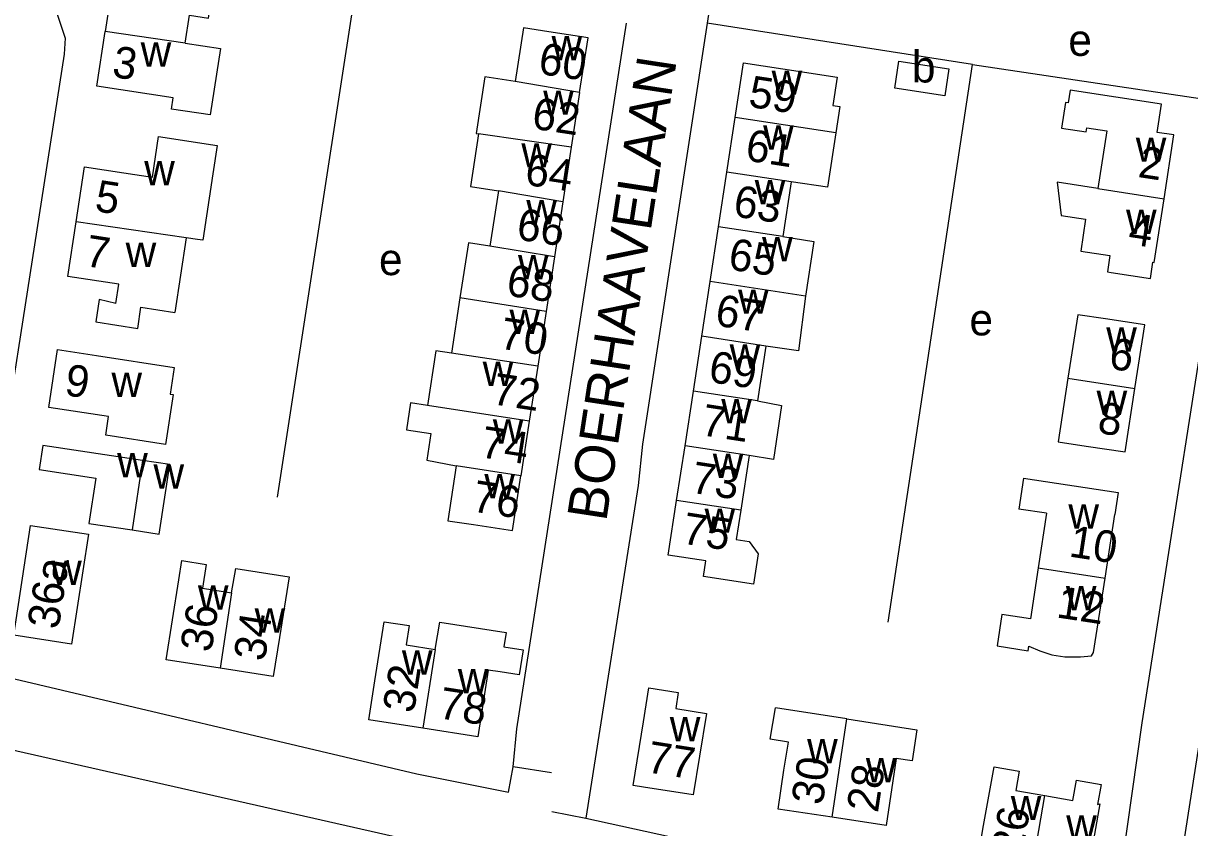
# Model space of a CAD drawing. Extents: x 161093 to 163177, y 379000 to 380904.
# Drawn here: x 161921.7 to 162069, y 380393.8 to 380495.5 of the extents above; entities that cross this region are included whole.
import ezdxf

# ---------------------------------------------------------------- set-up
doc = ezdxf.new("R2010")
doc.units = 0
for name, color, linetype in [('BLT_Basislijn', 7, 'Continuous'), ('BLT_Bebouwing', 7, 'Continuous'), ('BLT_Centroide', 7, 'Continuous'), ('BLT_Huisnummer', 7, 'Continuous'), ('BLT_Huisnummer_ tussenligend', 7, 'Continuous'), ('BLT_Onderverdeling_panden', 7, 'Continuous'), ('BLT_Straatnaam', 7, 'Continuous')]:
    doc.layers.add(name, color=color, linetype=linetype)

msp = doc.modelspace()

# ---------------------------------------------------------------- linework, layer by layer
at = {"layer": 'BLT_Basislijn'}
for p, q in [((162011.73, 380519.84), (162008.05, 380495.48)), ((161953.76, 380435.58), (161963.84, 380501.05)), ((162041.6, 380490.28), (162008.05, 380495.48)), ((162041.6, 380490.28), (162080.66, 380484.4)), ((162080.1, 380468.07), (162066.51, 380380.82)), ((161988.39, 380400.71), (161983.54, 380401.47)), ((161988.42, 380395.82), (161992.72, 380394.99))]:
    msp.add_line(p, q, dxfattribs=at)
for points in [[(161922.51, 380507.63), (161922.58, 380506.72), (161926.97, 380493.62), (161926.83, 380491.57), (161914.93, 380415.47), (161916.11, 380414.16), (161917.48, 380413.33), (161971.38, 380400.58), (161982.94, 380398.28), (161983.54, 380401.47)], [(161983.54, 380401.47), (161984.03, 380406.27), (161997.87, 380495.51)], [(162008.05, 380495.48), (161999.88, 380442.25), (161999.34, 380437.05), (161992.72, 380394.99)], [(162030.93, 380419.77), (162041.6, 380490.28)], [(161992.72, 380394.99), (162053.82, 380381.59), (162056.59, 380381.51), (162058.47, 380382.47), (162059.9, 380384.99), (162063, 380407.02), (162073.67, 380475.15), (162080.66, 380484.4)], [(161790.41, 380429.73), (161841.6, 380420.4), (161892.77, 380409.85), (161973.76, 380391.48), (162004.17, 380383.95)]]:
    msp.add_lwpolyline(points, dxfattribs=at)
at = {"layer": 'BLT_Bebouwing'}
for p, q in [((162032.27, 380490.7), (162038.6, 380489.73)), ((161991.95, 380486.73), (161990.89, 380479.81)), ((162010.55, 380476.67), (162011.61, 380483.59)), ((161990.89, 380479.81), (161989.83, 380472.89)), ((162009.49, 380469.75), (162010.55, 380476.67)), ((161981.69, 380474.29), (161980.62, 380467.32)), ((162018.66, 380475.43), (162017.6, 380468.51)), ((161989.83, 380472.89), (161988.77, 380465.96)), ((161927.3, 380463.47), (161928.35, 380470.39)), ((162008.43, 380462.83), (162009.49, 380469.75)), ((161942.25, 380468.36), (161940.81, 380458.92)), ((161988.77, 380465.96), (161987.71, 380459.04)), ((161933.73, 380462.49), (161927.3, 380463.47)), ((162007.38, 380455.91), (162008.43, 380462.83)), ((161976.83, 380460.78), (161975.75, 380453.76)), ((161987.71, 380459.04), (161986.65, 380452.11)), ((162006.32, 380448.99), (162007.38, 380455.91)), ((162015.48, 380454.67), (162014.42, 380447.75)), ((161986.65, 380452.11), (161985.58, 380445.19)), ((162005.26, 380442.07), (162006.32, 380448.99)), ((161985.58, 380445.19), (161984.52, 380438.27)), ((162004.2, 380435.15), (162005.26, 380442.07)), ((162013.36, 380440.83), (162012.31, 380433.91)), ((162050.93, 380433.53), (162047.43, 380434.07))]:
    msp.add_line(p, q, dxfattribs=at)
for points in [[(161942.01, 380500), (161938, 380500.61), (161933.05, 380501.36), (161932, 380494.44)], [(161942.11, 380492.98), (161942.65, 380496.5), (161945.08, 380496.13), (161945.57, 380499.35), (161942.01, 380500)], [(161991.95, 380486.73), (161993.01, 380493.65), (161988.07, 380494.41), (161984.85, 380494.9), (161983.81, 380488.11)], [(161942.11, 380492.98), (161946.56, 380492.3), (161945.28, 380483.89), (161940.37, 380484.63), (161940.58, 380486.06), (161930.95, 380487.52), (161932, 380494.44)], [(162011.61, 380483.59), (162012.67, 380490.5), (162017.61, 380489.74), (162024.5, 380488.69), (162023.95, 380485.1), (162024.82, 380484.97), (162024.31, 380481.64)], [(162038.6, 380489.73), (162038.08, 380486.32), (162031.75, 380487.29), (162032.27, 380490.7)], [(161983.81, 380488.11), (161979.98, 380488.7), (161978.88, 380481.53), (161979.18, 380481.49)], [(162065.78, 380473.3), (162067.01, 380481.36), (162064.93, 380481.67), (162065.48, 380485.26), (162053.93, 380487.03), (162053.68, 380485.42), (162053.33, 380485.47), (162052.83, 380482.24), (162055.95, 380481.77), (162056.02, 380482.25), (162058.54, 380481.87), (162057.42, 380474.58)], [(161979.18, 380481.49), (161978.16, 380474.83), (161981.69, 380474.29)], [(162024.31, 380481.64), (162023.28, 380474.76), (162018.66, 380475.43)], [(161928.35, 380470.39), (161929.41, 380477.32), (161934.35, 380476.56), (161937.97, 380476.01), (161938.75, 380481.15), (161946.17, 380480.02), (161945.62, 380476.45), (161944.35, 380468.05), (161943.69, 380468.14), (161942.25, 380468.36)], [(162057.42, 380474.58), (162052.27, 380475.39), (162052.8, 380471.18), (162055.87, 380470.71), (162055.25, 380466.68), (162058.94, 380466.11), (162058.62, 380464.04), (162059.12, 380463.96), (162064.06, 380463.21), (162064.38, 380465.28), (162064.55, 380465.25), (162065.78, 380473.3)], [(162017.6, 380468.51), (162021.55, 380467.9), (162020.49, 380460.98)], [(161980.62, 380467.32), (161977.9, 380467.74), (161976.83, 380460.78)], [(161933.37, 380460.05), (161933.73, 380462.49)], [(162020.49, 380460.98), (162019.6, 380454.07), (162015.48, 380454.67)], [(161933.37, 380460.05), (161931.25, 380460.58), (161930.81, 380457.72), (161936.13, 380456.91), (161936.53, 380459.57), (161940.81, 380458.92)], [(162062.11, 380449.31), (162063.34, 380457.34), (162058.39, 380458.1), (162054.87, 380458.64), (162053.64, 380450.61)], [(161930.92, 380453.48), (161940.73, 380451.98), (161940.21, 380448.59), (161940.59, 380448.53), (161939.63, 380442.24), (161932.07, 380443.4), (161932.43, 380445.77), (161924.87, 380446.92), (161925.98, 380454.23), (161930.92, 380453.48)], [(161975.75, 380453.76), (161973.8, 380454.06), (161972.74, 380447.15)], [(162053.64, 380450.61), (162052.41, 380442.57), (162055.93, 380442.03), (162060.88, 380441.28), (162062.11, 380449.31)], [(161970.6, 380447.48), (161970.08, 380444.1), (161973.15, 380443.63), (161972.63, 380440.25), (161976.36, 380439.52)], [(161972.74, 380447.15), (161970.6, 380447.48)], [(162014.42, 380447.75), (162017.47, 380447.14), (162016.43, 380440.34), (162013.36, 380440.83)], [(161936.74, 380440.2), (161924.14, 380442.12), (161923.67, 380439.05), (161930.81, 380437.96)], [(161935.4, 380431.42), (161938.82, 380430.9), (161940.16, 380439.68), (161936.74, 380440.2)], [(161976.36, 380439.52), (161975.3, 380432.59), (161978.52, 380432.1), (161983.46, 380431.34), (161984.52, 380438.27)], [(161930.81, 380437.96), (161929.94, 380432.25), (161935.4, 380431.42)], [(162048.03, 380437.99), (162047.43, 380434.07)], [(162048.03, 380437.99), (162059.99, 380436.16), (162059.57, 380433.39)], [(162012.31, 380433.91), (162011.74, 380430.21), (162013.38, 380429.96), (162014.5, 380428.4), (162013.91, 380424.55), (162007.58, 380425.52), (162007.88, 380427.5), (162003.14, 380428.23), (162004.2, 380435.15)], [(162050.93, 380433.53), (162049.87, 380426.63)], [(162058.33, 380425.33), (162059.57, 380433.39)], [(161922.59, 380431.99), (161929.88, 380430.88), (161927.77, 380416.99), (161920.48, 380418.1), (161922.59, 380431.99)], [(161946.54, 380413.95), (161939.73, 380415.02), (161941.31, 380425.1), (161941.69, 380427.54), (161944.77, 380427.06), (161944.29, 380424.04), (161947.98, 380423.46)], [(161947.98, 380423.46), (161948.52, 380426.54), (161955.23, 380425.49), (161954.03, 380417.84), (161953.25, 380412.9), (161946.54, 380413.95)], [(162049.87, 380426.63), (162048.89, 380420.19), (162045.3, 380420.74), (162044.69, 380416.75), (162048.6, 380416.15), (162048.68, 380416.71), (162050.1, 380416.13), (162051.6, 380415.64), (162053.25, 380415.39), (162055.21, 380415.38), (162056.6, 380415.51), (162056.89, 380415.93), (162058.33, 380425.33)], [(161972.13, 380406.35), (161965.32, 380407.41), (161966.09, 380412.35), (161967.25, 380419.8), (161970.41, 380419.32), (161970.03, 380416.88), (161973.68, 380416.31)], [(161973.68, 380416.31), (161974.29, 380419.76), (161982.66, 380418.46), (161982.38, 380416.64), (161984.8, 380416.27), (161984.31, 380413.11), (161981.89, 380413.48), (161980.41, 380413.71), (161979.1, 380405.27), (161972.13, 380406.35)], [(162000, 380407.14), (162000.69, 380411.45), (162004.41, 380410.85), (162004.09, 380408.83), (162007.97, 380408.21), (162007.11, 380402.84), (162006.31, 380397.91), (162000, 380398.91)], [(162018.34, 380404.58), (162016.03, 380404.97), (162016.69, 380408.94)], [(162025.71, 380407.53), (162016.69, 380408.94)], [(162000, 380398.91), (161998.71, 380399.11), (162000, 380407.14)], [(162025.71, 380407.53), (162034.55, 380406.15), (162033.96, 380402.21), (162031.94, 380402.51), (162030.67, 380394.06), (162023.84, 380395.09)], [(162023.84, 380395.09), (162017.01, 380396.11), (162017.75, 380401.06), (162018.34, 380404.58)], [(162049.02, 380387.92), (162042.12, 380389.12), (162042.98, 380394.05), (162044.32, 380401.47), (162047.48, 380400.92), (162047.05, 380398.47), (162050.73, 380397.83)], [(162050.73, 380397.83), (162054.27, 380397.22), (162054.72, 380399.77), (162057.82, 380399.23), (162057.38, 380396.7), (162057.65, 380396.8), (162055.91, 380386.73), (162049.02, 380387.92)]]:
    msp.add_lwpolyline(points, dxfattribs=at)
at = {"layer": 'BLT_Onderverdeling_panden'}
for p, q in [((161942.11, 380492.98), (161932, 380494.44)), ((161991.95, 380486.73), (161983.81, 380488.11)), ((162024.31, 380481.64), (162011.61, 380483.59)), ((161990.89, 380479.81), (161979.18, 380481.49)), ((162018.66, 380475.43), (162010.55, 380476.67)), ((161989.83, 380472.89), (161981.69, 380474.29)), ((162057.42, 380474.58), (162065.78, 380473.3)), ((161942.25, 380468.36), (161928.35, 380470.39)), ((162017.6, 380468.51), (162009.49, 380469.75)), ((161988.77, 380465.96), (161980.62, 380467.32)), ((162020.49, 380460.98), (162008.43, 380462.83)), ((161987.71, 380459.04), (161976.83, 380460.78)), ((162015.48, 380454.67), (162007.38, 380455.91)), ((161986.65, 380452.11), (161975.75, 380453.76)), ((162053.64, 380450.61), (162062.11, 380449.31)), ((162014.42, 380447.75), (162006.32, 380448.99)), ((161985.58, 380445.19), (161972.74, 380447.15)), ((162013.36, 380440.83), (162005.26, 380442.07)), ((161936.74, 380440.2), (161935.4, 380431.42)), ((161984.52, 380438.27), (161976.36, 380439.52)), ((162012.31, 380433.91), (162004.2, 380435.15)), ((162049.87, 380426.63), (162058.33, 380425.33)), ((161947.98, 380423.46), (161946.54, 380413.95)), ((161973.68, 380416.31), (161972.13, 380406.35)), ((162023.84, 380395.09), (162025.71, 380407.53)), ((162049.02, 380387.92), (162050.73, 380397.83))]:
    msp.add_line(p, q, dxfattribs=at)

# ---------------------------------------------------------------- texts
at = {"layer": 'BLT_Centroide'}
for s, p in [('w', (161988.4, 380490.81)), ('e', (162053.69, 380491.36)), ('w', (161936.49, 380490)), ('b', (162033.93, 380488)), ('w', (162016.2, 380486.44)), ('w', (161987.34, 380483.91)), ('w', (162015.13, 380479.5)), ('w', (161984.58, 380477.25)), ('w', (162062.21, 380477.97)), ('w', (161936.94, 380475)), ('w', (162014.07, 380472.59)), ('w', (161985.21, 380470.06)), ('w', (162060.98, 380468.86)), ('w', (162015, 380465.38)), ('w', (161934.59, 380464.66)), ('e', (161966.6, 380463.64)), ('w', (161984.16, 380463.12)), ('w', (162011.96, 380458.75)), ('w', (161983.09, 380456.19)), ('e', (162041.2, 380456.02)), ('w', (162058.48, 380453.97)), ('w', (162010.9, 380451.81)), ('w', (161979.7, 380449.62)), ('w', (161932.8, 380448.25)), ('w', (162057.26, 380445.94)), ('w', (162009.84, 380444.91)), ('w', (161980.98, 380442.34)), ('w', (161933.52, 380438.06)), ('w', (162008.77, 380438)), ('w', (161938.11, 380436.64)), ('w', (161979.91, 380435.44)), ('w', (162053.7, 380431.58)), ('w', (162007.73, 380431.06)), ('w', (161925.19, 380424.48)), ('w', (161943.72, 380421.33)), ('w', (162053.38, 380421.27)), ('w', (161950.89, 380418.44)), ('w', (161969.5, 380413.11)), ('w', (161976.56, 380410.77)), ('w', (162003.34, 380404.7)), ('w', (162020.69, 380401.92)), ('w', (162028.11, 380399.52)), ('w', (162046.42, 380394.73)), ('w', (162053.42, 380392.27))]:
    msp.add_text(s, height=4, dxfattribs=at).set_placement(p)
at = {"layer": 'BLT_Huisnummer'}
for s, rotation, p in [('3', 351.3401, (161932.76, 380488.72)), ('60', 351.2876, (161986.6, 380489.12)), ('59', 351.2979, (162013.15, 380484.95)), ('2', 351.293, (162062.38, 380476.06)), ('64', 351.2855, (161984.89, 380475.1)), ('5', 351.3365, (161930.57, 380471.75)), ('63', 351.2979, (162011.23, 380471.1)), ('4', 351.3026, (162061.13, 380467.59)), ('7', 351.3383, (161929.33, 380464.81)), ('68', 351.2844, (161982.56, 380461.09)), ('67', 351.2969, (162008.94, 380457.29)), ('6', 351.2889, (162058.68, 380451.84)), ('9', 351.3401, (161926.74, 380448.49)), ('72', 351.2834, (161980.76, 380447.34)), ('8', 351.2913, (162057.25, 380443.71)), ('71', 351.2969, (162007.17, 380443.42)), ('76', 351.2913, (161978.24, 380433.78)), ('75', 351.293, (162004.76, 380429.72)), ('10', 351.2971, (162053.66, 380428.08)), ('36a', 81.3391, (161926.11, 380418.76)), ('12', 351.3026, (162052.07, 380420.38)), ('36', 81.0291, (161945.41, 380415.84)), ('34', 81.084, (161952.16, 380414.71)), ('32', 81.1704, (161971, 380408.15)), ('78', 351.1723, (161974, 380407.64)), ('77', 351.0003, (162000.29, 380400.81)), ('30', 81.4283, (162022.63, 380396.52)), ('28', 81.4211, (162029.62, 380395.57)), ('26', 80.1732, (162047.86, 380390.17))]:
    msp.add_text(s, height=4, rotation=rotation, dxfattribs=at).set_placement(p)
at = {"layer": 'BLT_Huisnummer_ tussenligend'}
for s, rotation, p in [('62', 351.2876, (161985.78, 380482.2)), ('61', 351.2979, (162012.76, 380478.17)), ('66', 351.2855, (161983.84, 380468.18)), ('65', 351.2979, (162010.6, 380464.39)), ('70', 351.2844, (161981.71, 380454.38)), ('69', 351.2969, (162008.11, 380450.16)), ('74', 351.2834, (161979.28, 380440.63)), ('73', 351.2969, (162005.89, 380436.15))]:
    msp.add_text(s, height=4, rotation=rotation, dxfattribs=at).set_placement(p)
at = {"layer": 'BLT_Straatnaam'}
msp.add_text('BOERHAAVELAAN', height=5, rotation=81.312, dxfattribs=at).set_placement((161995.3, 380432.39))

doc.saveas('drawing.dxf')
